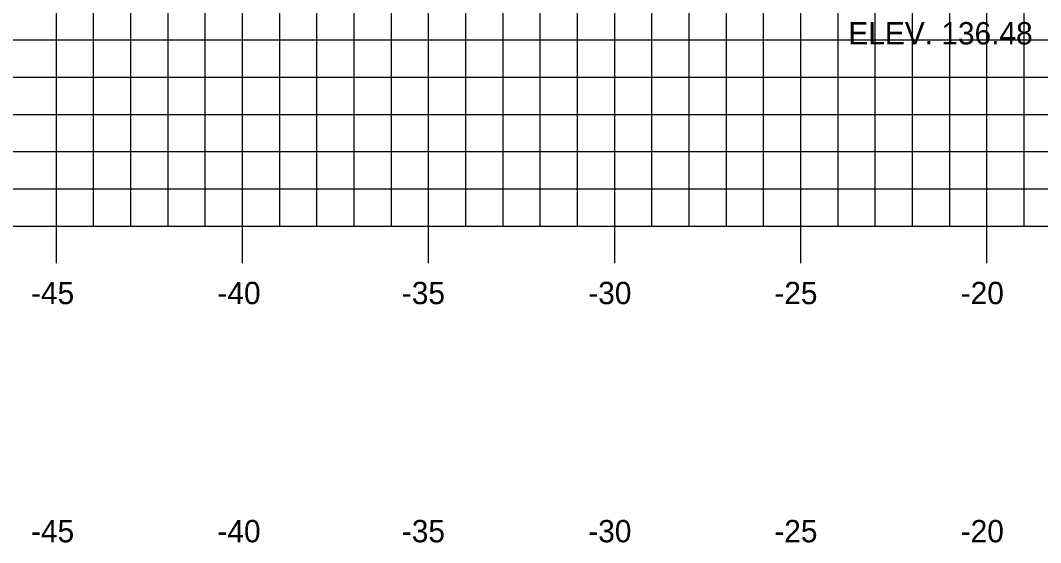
# Model space of a CAD drawing. Extents: x 1146525 to 1146695, y 608981 to 609091.
# Drawn here: x 1146561.7 to 1146589.11, y 609046.83 to 609060.86 of the extents above; entities that cross this region are included whole.
import ezdxf

# ---------------------------------------------------------------- set-up
doc = ezdxf.new("R2010")
doc.units = 0
for name, color, linetype in [('D_Text_Standard', 7, 'Continuous'), ('H_V ANNOTATION', 7, 'Continuous'), ('MAJOR', 7, 'Continuous'), ('MINOR', 7, 'Continuous')]:
    doc.layers.add(name, color=color, linetype=linetype)

msp = doc.modelspace()

# ---------------------------------------------------------------- linework, layer by layer
at = {"layer": 'MAJOR'}
for p, q in [((1146562.671, 609055.335), (1146562.671, 609075.335)), ((1146567.671, 609055.335), (1146567.671, 609075.335)), ((1146572.671, 609055.335), (1146572.671, 609075.335)), ((1146577.671, 609055.335), (1146577.671, 609075.335)), ((1146582.671, 609055.335), (1146582.671, 609075.335)), ((1146587.671, 609055.335), (1146587.671, 609075.335)), ((1146537.671, 609060.335), (1146677.671, 609060.335)), ((1146537.671, 609055.335), (1146677.671, 609055.335)), ((1146537.671, 609055.335), (1146677.671, 609055.335)), ((1146562.671, 609054.333), (1146562.671, 609055.335)), ((1146567.671, 609054.333), (1146567.671, 609055.335)), ((1146572.671, 609054.333), (1146572.671, 609055.335)), ((1146577.671, 609054.333), (1146577.671, 609055.335)), ((1146582.671, 609054.333), (1146582.671, 609055.335)), ((1146587.671, 609054.333), (1146587.671, 609055.335))]:
    msp.add_line(p, q, dxfattribs=at)
at = {"layer": 'MINOR'}
for p, q in [((1146563.671, 609055.335), (1146563.671, 609075.335)), ((1146564.671, 609055.335), (1146564.671, 609075.335)), ((1146565.671, 609055.335), (1146565.671, 609075.335)), ((1146566.671, 609055.335), (1146566.671, 609075.335)), ((1146568.671, 609055.335), (1146568.671, 609075.335)), ((1146569.671, 609055.335), (1146569.671, 609075.335)), ((1146570.671, 609055.335), (1146570.671, 609075.335)), ((1146571.671, 609055.335), (1146571.671, 609075.335)), ((1146573.671, 609055.335), (1146573.671, 609075.335)), ((1146574.671, 609055.335), (1146574.671, 609075.335)), ((1146575.671, 609055.335), (1146575.671, 609075.335)), ((1146576.671, 609055.335), (1146576.671, 609075.335)), ((1146578.671, 609055.335), (1146578.671, 609075.335)), ((1146579.671, 609055.335), (1146579.671, 609075.335)), ((1146580.671, 609055.335), (1146580.671, 609075.335)), ((1146581.671, 609055.335), (1146581.671, 609075.335)), ((1146583.671, 609055.335), (1146583.671, 609075.335)), ((1146584.671, 609055.335), (1146584.671, 609075.335)), ((1146585.671, 609055.335), (1146585.671, 609075.335)), ((1146586.671, 609055.335), (1146586.671, 609075.335)), ((1146588.671, 609055.335), (1146588.671, 609075.335)), ((1146537.671, 609059.335), (1146677.671, 609059.335)), ((1146537.671, 609058.335), (1146677.671, 609058.335)), ((1146537.671, 609057.335), (1146677.671, 609057.335)), ((1146537.671, 609056.335), (1146677.671, 609056.335))]:
    msp.add_line(p, q, dxfattribs=at)

# ---------------------------------------------------------------- texts
at = {"layer": 'D_Text_Standard'}
msp.add_text('ELEV. 136.48', height=0.6, dxfattribs=at).set_placement((1146583.947, 609060.216))
at = {"layer": 'H_V ANNOTATION'}
for s, p in [('-45', (1146561.989, 609053.235)), ('-40', (1146566.997, 609053.235)), ('-35', (1146571.951, 609053.235)), ('-30', (1146576.959, 609053.235)), ('-25', (1146581.957, 609053.235)), ('-20', (1146586.965, 609053.235)), ('-45', (1146561.989, 609046.835)), ('-40', (1146566.997, 609046.835)), ('-35', (1146571.951, 609046.835)), ('-30', (1146576.959, 609046.835)), ('-25', (1146581.957, 609046.835)), ('-20', (1146586.965, 609046.835))]:
    msp.add_text(s, height=0.6, dxfattribs=at).set_placement(p)

doc.saveas('drawing.dxf')
